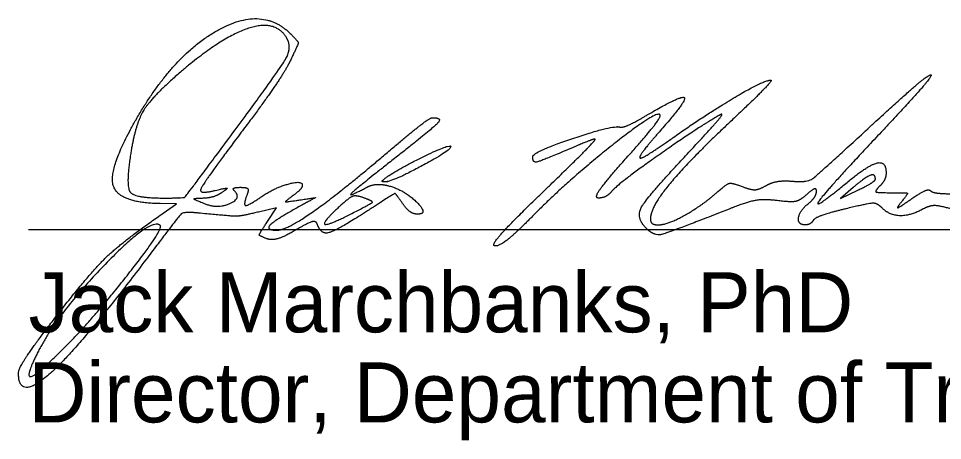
# Model space of a CAD drawing. Extents: x -13.1 to 43.1, y 0 to 22.
# Drawn here: x 25.096 to 27.252, y 7.964 to 8.948 of the extents above; entities that cross this region are included whole.
import ezdxf

# ---------------------------------------------------------------- set-up
doc = ezdxf.new("R2010")
doc.units = 0
doc.layers.add('SH_Data', color=7, linetype='Continuous')
doc.layers.add('SH_Text', color=7, linetype='Continuous')

msp = doc.modelspace()

# ---------------------------------------------------------------- linework, layer by layer
at = {"layer": 'SH_Data'}
msp.add_line((25.1191, 8.4565), (28.6191, 8.4565), dxfattribs=at)
at = {"layer": 'SH_Text'}
for p, q in [((25.5813, 8.6615), (25.5813, 8.6615)), ((25.9467, 8.5717), (25.9467, 8.5717)), ((27.0956, 8.5737), (27.0956, 8.5737)), ((26.3185, 8.5426), (26.3185, 8.5426)), ((25.9019, 8.53), (25.9019, 8.53))]:
    msp.add_line(p, q, dxfattribs=at)
for points in [[(27.0439, 8.554), (27.0144, 8.5284), (27.055, 8.5481)], [(25.4337, 8.4946), (25.4644, 8.5158), (25.4265, 8.5165)], [(25.6766, 8.4747), (25.6978, 8.5071), (25.6561, 8.497)]]:
    msp.add_lwpolyline(points, dxfattribs=at)
for points in [[(25.37, 8.7123), (25.4563, 8.8627), (25.6644, 8.9787), (25.7301, 8.913)], [(25.7211, 8.9039), (25.6951, 8.9459), (25.5691, 8.9047), (25.4737, 8.8231)], [(25.7301, 8.913), (25.7488, 8.8943), (25.7489, 8.8892), (25.7306, 8.8508)], [(25.5813, 8.6615), (25.7027, 8.825), (25.7351, 8.8812), (25.7211, 8.9039)], [(25.7306, 8.8508), (25.7196, 8.8278), (25.6679, 8.7522), (25.6156, 8.6829)], [(25.4737, 8.8231), (25.4071, 8.766), (25.3682, 8.7019), (25.3571, 8.6307)], [(26.6238, 8.6708), (26.7043, 8.7274), (26.8356, 8.8046), (26.8513, 8.8046)], [(26.8513, 8.8046), (26.8562, 8.8046), (26.8149, 8.762), (26.7595, 8.7099)], [(27.078, 8.6912), (27.153, 8.7603), (27.2191, 8.8169), (27.2248, 8.817)], [(27.2248, 8.817), (27.2305, 8.8171), (27.1785, 8.7569), (27.1092, 8.6833)], [(26.5648, 8.7243), (26.6436, 8.7704), (26.6558, 8.7572), (26.5966, 8.6899)], [(25.9602, 8.6388), (26.0106, 8.6817), (26.0561, 8.7168), (26.0613, 8.7169)], [(26.0613, 8.7169), (26.0861, 8.7174), (26.0628, 8.6919), (25.9769, 8.6246)], [(26.5929, 8.724), (26.5833, 8.7337), (26.3735, 8.5667), (26.2956, 8.4874)], [(26.7331, 8.7236), (26.6841, 8.6958), (26.4958, 8.5636), (26.4825, 8.5476)], [(26.4992, 8.6951), (26.5047, 8.6932), (26.5343, 8.7064), (26.5648, 8.7243)], [(26.5151, 8.6237), (26.5614, 8.6754), (26.5964, 8.7205), (26.5929, 8.724)], [(26.668, 8.6446), (26.7141, 8.6939), (26.7435, 8.7294), (26.7331, 8.7236)], [(25.4265, 8.5165), (25.3286, 8.5182), (25.3052, 8.5993), (25.37, 8.7123)], [(26.2958, 8.6265), (26.2961, 8.637), (26.4834, 8.7002), (26.4992, 8.6951)], [(26.7595, 8.7099), (26.6599, 8.6162), (26.5706, 8.508), (26.5706, 8.4811)], [(25.6156, 8.6829), (25.5634, 8.6135), (25.5206, 8.5529), (25.5206, 8.5481)], [(26.5966, 8.6899), (26.5686, 8.6581), (26.5456, 8.6284), (26.5456, 8.6239)], [(26.5456, 8.6239), (26.5456, 8.6195), (26.5808, 8.6406), (26.6238, 8.6708)], [(26.903, 8.5688), (26.9365, 8.566), (26.96, 8.5824), (27.078, 8.6912)], [(27.1092, 8.6833), (26.9796, 8.5458), (26.9476, 8.4985), (27.0297, 8.5662)], [(25.4352, 8.5296), (25.4819, 8.5296), (25.4864, 8.5337), (25.5813, 8.6615)], [(25.9467, 8.5717), (25.9671, 8.5895), (26.0991, 8.6553), (26.1043, 8.6502)], [(26.1043, 8.6502), (26.1104, 8.644), (25.9678, 8.5671), (25.9502, 8.5671)], [(26.3185, 8.5426), (26.3895, 8.6111), (26.4448, 8.6671), (26.4414, 8.6671)], [(26.4414, 8.6671), (26.438, 8.6671), (26.409, 8.6559), (26.3769, 8.6421)], [(25.3571, 8.6307), (25.3457, 8.5573), (25.3671, 8.5296), (25.4352, 8.5296)], [(25.6988, 8.4546), (25.7219, 8.4546), (25.8479, 8.5434), (25.9602, 8.6388)], [(26.3769, 8.6421), (26.3143, 8.6153), (26.2955, 8.6117), (26.2958, 8.6265)], [(26.5609, 8.459), (26.5357, 8.4842), (26.5646, 8.5343), (26.668, 8.6446)], [(25.9769, 8.6246), (25.8837, 8.5516), (25.8622, 8.53), (25.9061, 8.5535)], [(26.4492, 8.5296), (26.4389, 8.5296), (26.4678, 8.5709), (26.5151, 8.6237)], [(27.0297, 8.5662), (27.0781, 8.6061), (27.1206, 8.6165), (27.1206, 8.5884)], [(27.0956, 8.5737), (27.0956, 8.5872), (27.0716, 8.578), (27.0439, 8.554)], [(27.1206, 8.5884), (27.1206, 8.5794), (27.1139, 8.5654), (27.1056, 8.5571)], [(25.6647, 8.534), (25.6936, 8.5538), (25.7581, 8.5713), (25.7581, 8.5594)], [(25.9502, 8.5671), (25.9454, 8.5671), (25.9438, 8.5692), (25.9467, 8.5717)], [(26.7281, 8.5446), (26.7484, 8.5627), (26.7613, 8.5653), (26.785, 8.5563)], [(26.84, 8.5583), (26.8534, 8.5659), (26.8818, 8.5706), (26.903, 8.5688)], [(27.055, 8.5481), (27.0774, 8.5589), (27.0956, 8.5704), (27.0956, 8.5737)], [(25.5206, 8.5481), (25.5206, 8.5433), (25.5361, 8.543), (25.555, 8.5474)], [(25.5706, 8.5427), (25.5603, 8.5357), (25.5406, 8.5296), (25.5269, 8.529)], [(25.5311, 8.5163), (25.5609, 8.5044), (25.6172, 8.5289), (25.5997, 8.5464)], [(25.555, 8.5474), (25.5805, 8.5533), (25.5846, 8.5521), (25.5706, 8.5427)], [(25.5997, 8.5464), (25.5952, 8.5509), (25.6015, 8.5546), (25.6136, 8.5546)], [(25.6136, 8.5546), (25.6282, 8.5546), (25.6333, 8.5482), (25.6286, 8.5359)], [(25.7581, 8.5594), (25.7581, 8.5548), (25.7484, 8.544), (25.7365, 8.5353)], [(25.9061, 8.5535), (25.9188, 8.5603), (25.9427, 8.5624), (25.9592, 8.5582)], [(25.9923, 8.5168), (25.9754, 8.5409), (25.9734, 8.5404), (25.9076, 8.498)], [(25.9592, 8.5582), (25.9953, 8.549), (26.0537, 8.4921), (26.027, 8.4921)], [(26.2081, 8.4178), (26.1978, 8.418), (26.2475, 8.4742), (26.3185, 8.5426)], [(26.4825, 8.5476), (26.4743, 8.5377), (26.4593, 8.5296), (26.4492, 8.5296)], [(26.5887, 8.4671), (26.6104, 8.4671), (26.6917, 8.5123), (26.7281, 8.5446)], [(26.785, 8.5563), (26.8052, 8.5486), (26.824, 8.5493), (26.84, 8.5583)], [(26.9581, 8.5456), (26.9581, 8.5527), (26.948, 8.5493), (26.9356, 8.5381)], [(26.9394, 8.5171), (26.9497, 8.5257), (26.9581, 8.5385), (26.9581, 8.5456)], [(27.1056, 8.5571), (27.094, 8.5455), (27.0999, 8.5421), (27.1322, 8.5421)], [(27.1322, 8.5421), (27.1697, 8.5421), (27.1721, 8.5401), (27.1565, 8.5207)], [(27.1783, 8.5266), (27.1997, 8.5416), (27.2204, 8.5507), (27.2243, 8.5467)], [(27.2243, 8.5467), (27.2283, 8.5428), (27.2515, 8.5396), (27.2761, 8.5396)], [(25.5269, 8.529), (25.5045, 8.5281), (25.5049, 8.5268), (25.5311, 8.5163)], [(25.6286, 8.5359), (25.6197, 8.5126), (25.6325, 8.5119), (25.6647, 8.534)], [(25.7365, 8.5353), (25.7176, 8.5215), (25.7196, 8.5202), (25.7521, 8.5251)], [(25.7521, 8.5251), (25.7889, 8.5307), (25.7888, 8.5304), (25.7433, 8.5053)], [(25.9019, 8.53), (25.8847, 8.5364), (25.8682, 8.5312), (25.8488, 8.5135)], [(25.8738, 8.4937), (25.9201, 8.5174), (25.9237, 8.522), (25.9019, 8.53)], [(26.8661, 8.5236), (26.8368, 8.5274), (26.797, 8.5209), (26.7605, 8.5065)], [(26.9356, 8.5381), (26.9199, 8.5239), (26.8986, 8.5195), (26.8661, 8.5236)], [(27.1565, 8.5207), (27.1445, 8.5057), (27.151, 8.5075), (27.1783, 8.5266)], [(25.7433, 8.5053), (25.6923, 8.4771), (25.6725, 8.4546), (25.6988, 8.4546)], [(25.9076, 8.498), (25.8388, 8.4537), (25.8013, 8.4439), (25.7932, 8.4683)], [(25.8488, 8.5135), (25.8045, 8.473), (25.8158, 8.4641), (25.8738, 8.4937)], [(26.027, 8.4921), (26.0174, 8.4921), (26.0018, 8.5032), (25.9923, 8.5168)], [(26.7605, 8.5065), (26.6144, 8.4488), (26.5794, 8.4405), (26.5609, 8.459)], [(26.9324, 8.4671), (26.914, 8.4671), (26.9186, 8.4999), (26.9394, 8.5171)], [(27.0267, 8.5046), (26.9884, 8.4954), (26.9541, 8.4832), (26.9506, 8.4775)], [(27.111, 8.5067), (27.0999, 8.5178), (27.0799, 8.5173), (27.0267, 8.5046)], [(27.2074, 8.5042), (27.1766, 8.4877), (27.1288, 8.489), (27.111, 8.5067)], [(27.2718, 8.5043), (27.245, 8.512), (27.2219, 8.512), (27.2074, 8.5042)], [(25.1828, 8.2524), (25.2604, 8.3529), (25.3405, 8.4302), (25.4337, 8.4946)], [(25.5149, 8.4947), (25.4815, 8.498), (25.4698, 8.4875), (25.3931, 8.3859)], [(25.6561, 8.497), (25.6158, 8.4873), (25.5934, 8.4869), (25.5149, 8.4947)], [(26.2956, 8.4874), (26.2578, 8.449), (26.2185, 8.4176), (26.2081, 8.4178)], [(26.5706, 8.4811), (26.5706, 8.4734), (26.5788, 8.4671), (26.5887, 8.4671)], [(26.9506, 8.4775), (26.947, 8.4718), (26.9389, 8.4671), (26.9324, 8.4671)], [(25.4266, 8.4654), (25.4057, 8.4863), (25.1871, 8.2606), (25.1408, 8.1702)], [(25.2109, 8.189), (25.2785, 8.2581), (25.4343, 8.4577), (25.4266, 8.4654)], [(25.6754, 8.4347), (25.6573, 8.4417), (25.6574, 8.4453), (25.6766, 8.4747)], [(25.742, 8.4545), (25.7164, 8.4394), (25.6864, 8.4305), (25.6754, 8.4347)], [(25.7932, 8.4683), (25.7903, 8.4768), (25.7711, 8.4717), (25.742, 8.4545)], [(25.3931, 8.3859), (25.2407, 8.1838), (25.0956, 8.0551), (25.0956, 8.1221)], [(25.0956, 8.1221), (25.0956, 8.1318), (25.1349, 8.1904), (25.1828, 8.2524)], [(25.1408, 8.1702), (25.1096, 8.1093), (25.1412, 8.1177), (25.2109, 8.189)]]:
    msp.add_open_spline(points, degree=2, dxfattribs=at)

# ---------------------------------------------------------------- texts
for s, p in [('Jack Marchbanks, PhD', (25.1191, 8.2165)), ('Director, Department of Transportation', (25.1191, 8.0065))]:
    msp.add_text(s, height=0.14, dxfattribs=at).set_placement(p)

doc.saveas('drawing.dxf')
